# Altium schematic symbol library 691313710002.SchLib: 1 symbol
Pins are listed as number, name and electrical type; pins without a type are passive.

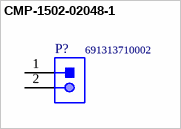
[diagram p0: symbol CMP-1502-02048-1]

## CMP-1502-02048-1
designator P?, comment 691313710002
Serie 3137 - 5.00mm Close Horizontal PCB Header WR-TBL, 2 pin; Manufacturer: Wurth Elektronik; Gender: Male; Pin Number: 2
footprint 691313710002 (5.00mm - Closed Horizhontal PCB Header - -02p)
pins: 1, 2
